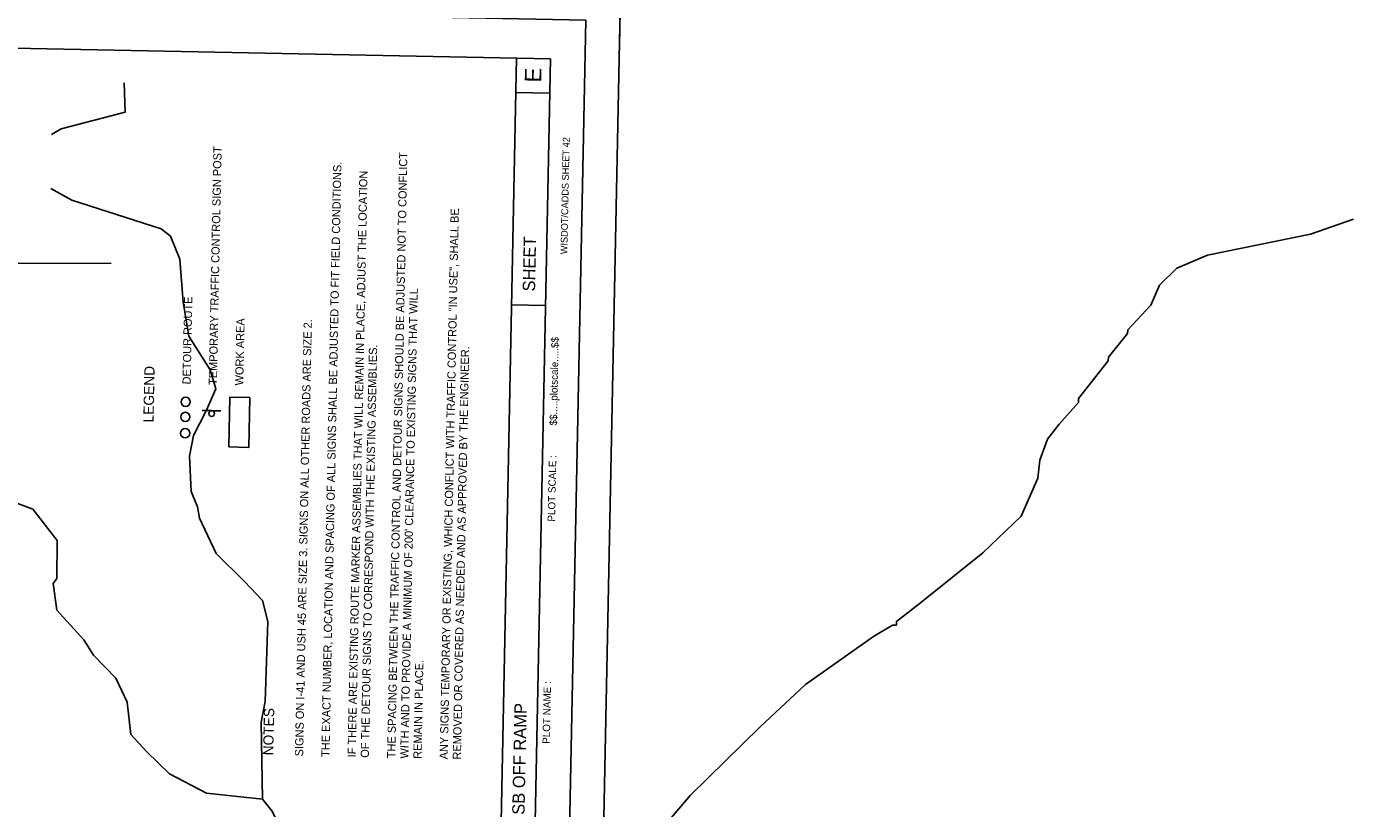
# Model space of a CAD drawing. Extents: x 331323 to 388339, y 121519 to 205315.
# Drawn here: x 363194 to 374815, y 143362 to 150213 of the extents above; entities that cross this region are included whole.
import ezdxf

# ---------------------------------------------------------------- set-up
doc = ezdxf.new("R2010")
doc.units = 0
for name, color, linetype in [('CA-TEXT', 7, 'Continuous'), ('CE-TOPO-CONC-SLAB', 7, 'Continuous'), ('Level 3', 7, 'Continuous'), ('Level 57', 7, 'Continuous'), ('P_RDWY_Text', 7, 'Continuous'), ('P_TC', 7, 'Continuous'), ('PLT_Sheet_Border', 7, 'Continuous'), ('PLT_Sheet_Info', 7, 'Continuous'), ('SIGNS-POLES', 7, 'Continuous')]:
    doc.layers.add(name, color=color, linetype=linetype)

msp = doc.modelspace()

# ---------------------------------------------------------------- linework, layer by layer
at = {"layer": 'CE-TOPO-CONC-SLAB'}
for centre in [(364588, 146925), (364585, 146793), (364583, 146650)]:
    msp.add_circle(centre, 40.2, dxfattribs=at)
at = {"layer": 'Level 3'}
msp.add_line((363934, 148140), (355745, 148126), dxfattribs=at)
at = {"layer": 'Level 57'}
for points in [[(364048, 149719), (364057, 149462), (363496, 149317), (363413, 149268)], [(363408, 148793), (363591, 148691), (364372, 148442), (364455, 148375), (364537, 148174), (364567, 147799), (364614, 147499), (364803, 147205), (364851, 147038), (364766, 146847), (364656, 146631), (364621, 146448), (364635, 146140), (364692, 146006), (364708, 145906), (364855, 145596), (365103, 145352), (365260, 145184), (365308, 145000), (365285, 144301), (365250, 144118), (365260, 143443)], [(373116, 147947), (373268, 148095), (373536, 148209), (374438, 148393), (374815, 148526)], [(370812, 144967), (370812, 145001), (371022, 145165), (371569, 145602), (371905, 145924), (372050, 146256), (372068, 146414), (372136, 146597), (372238, 146729), (372406, 146920), (372407, 146953), (372668, 147284), (372669, 147317), (372837, 147524), (372838, 147557), (373040, 147772), (373116, 147947)], [(363108, 146037), (363249, 145986), (363463, 145709), (363460, 145376), (363426, 145334), (363458, 145101), (363697, 144840), (363779, 144706), (363977, 144504), (364076, 144295), (364106, 144011)], [(367015, 141052), (367166, 141192), (367293, 141374), (367696, 141687), (367772, 141761), (367857, 141961), (367874, 142044), (367928, 142418), (367979, 142535), (368081, 142684), (368282, 142840), (368676, 143087), (369005, 143475), (369620, 144078), (370015, 144450), (370611, 144869), (370779, 144968), (370812, 144967)], [(364106, 144011), (364247, 143860), (364445, 143667), (364769, 143497), (365260, 143443)], [(364906, 142137), (364925, 142346), (365009, 142461), (365403, 142641), (365487, 142740), (365490, 143049), (365343, 143342), (365260, 143443)]]:
    msp.add_lwpolyline(points, dxfattribs=at)
at = {"layer": 'P_RDWY_Text'}
msp.add_lwpolyline([(354791, 130528), (355202, 150924), (368399, 150658), (367988, 130262)], close=True, dxfattribs=at)
at = {"layer": 'P_TC'}
msp.add_lwpolyline([(364966, 146530), (364975, 146966), (365149, 146962), (365140, 146526)], close=True, dxfattribs=at)
at = {"layer": 'PLT_Sheet_Border'}
for points in [[(367988, 130262), (368399, 150658), (355202, 150924), (354791, 130528)], [(367691, 130412), (368091, 150268), (355494, 150522), (355094, 130666)]]:
    msp.add_lwpolyline(points, close=True, dxfattribs=at)
at = {"layer": 'PLT_Sheet_Info'}
for p, q in [((368387, 150058), (368399, 150658)), ((367784, 149929), (355787, 150171)), ((367104, 131039), (367484, 149935)), ((367404, 131033), (367784, 149929)), ((367778, 149629), (367478, 149635)), ((367741, 147769), (367441, 147775))]:
    msp.add_line(p, q, dxfattribs=at)
at = {"layer": 'SIGNS-POLES'}
for p, q in [((364733, 146848), (364814, 146848)), ((364814, 146847), (364895, 146846))]:
    msp.add_line(p, q, dxfattribs=at)
msp.add_circle((364815, 146822), 25, dxfattribs=at)

# ---------------------------------------------------------------- texts
at = {"layer": 'CA-TEXT'}
for s, height, rotation, p in [('TEMPORARY TRAFFIC CONTROL SIGN POST', 72, 88.8468, (364861, 147072)), ('THE SPACING BETWEEN THE TRAFFIC CONTROL AND DETOUR SIGNS SHOULD BE ADJUSTED NOT TO CONFLICT', 72, 88.8462, (366423, 143802)), ('THE EXACT NUMBER, LOCATION AND SPACING OF ALL SIGNS SHALL BE ADJUSTED TO FIT FIELD CONDITIONS.', 72, 88.8462, (365847, 143813)), ('IF THERE ARE EXISTING ROUTE MARKER ASSEMBLIES THAT WILL REMAIN IN PLACE, ADJUST THE LOCATION ', 72, 88.8462, (366077, 143809)), ('ANY SIGNS TEMPORARY OR EXISTING, WHICH CONFLICT WITH TRAFFIC CONTROL "IN USE", SHALL BE', 72, 88.8462, (366883, 143792)), ('DETOUR ROUTE', 72, 88.8468, (364631, 147077)), ("WITH AND TO PROVIDE A MINIMUM OF 200' CLEARANCE TO EXISTING SIGNS THAT WILL", 72, 88.8462, (366538, 143799)), ('WORK AREA', 72, 88.8468, (365092, 147068)), ('SIGNS ON I-41 AND USH 45 ARE SIZE 3. SIGNS ON ALL OTHER ROADS ARE SIZE 2.', 72, 88.8462, (365616, 143818)), ('OF THE DETOUR SIGNS TO CORRESPOND WITH THE EXISTING ASSEMBLIES. ', 72, 88.8462, (366192, 143806)), ('REMOVED OR COVERED AS NEEDED AND AS APPROVED BY THE ENGINEER.', 72, 88.8462, (366998, 143790)), ('LEGEND', 90, 88.8468, (364306, 146744)), ('REMAIN IN PLACE.', 72, 88.8462, (366653, 143797)), ('NOTES', 90, 88.8468, (365355, 143827))]:
    msp.add_text(s, height=height, rotation=rotation, dxfattribs=at).set_placement(p)
at = {"layer": 'PLT_Sheet_Info'}
for s, height, p in [('E', 144, (367701, 149722)), ('WISDOT/CADDS SHEET 42', 60, (367930, 148218)), ('SHEET ', 108, (367647, 147891)), ('$$.....plotscale.....$$', 64.8, (367839, 146717)), ('PLOT SCALE : ', 64.8, (367822, 145875)), ('PLOT NAME :                      ', 64.8, (367777, 143928)), ('DETOUR ROUTE - STH 145 SB OFF RAMP                   ', 108, (367517, 141413))]:
    msp.add_text(s, height=height, rotation=88.8462, dxfattribs=at).set_placement(p)

doc.saveas('drawing.dxf')
